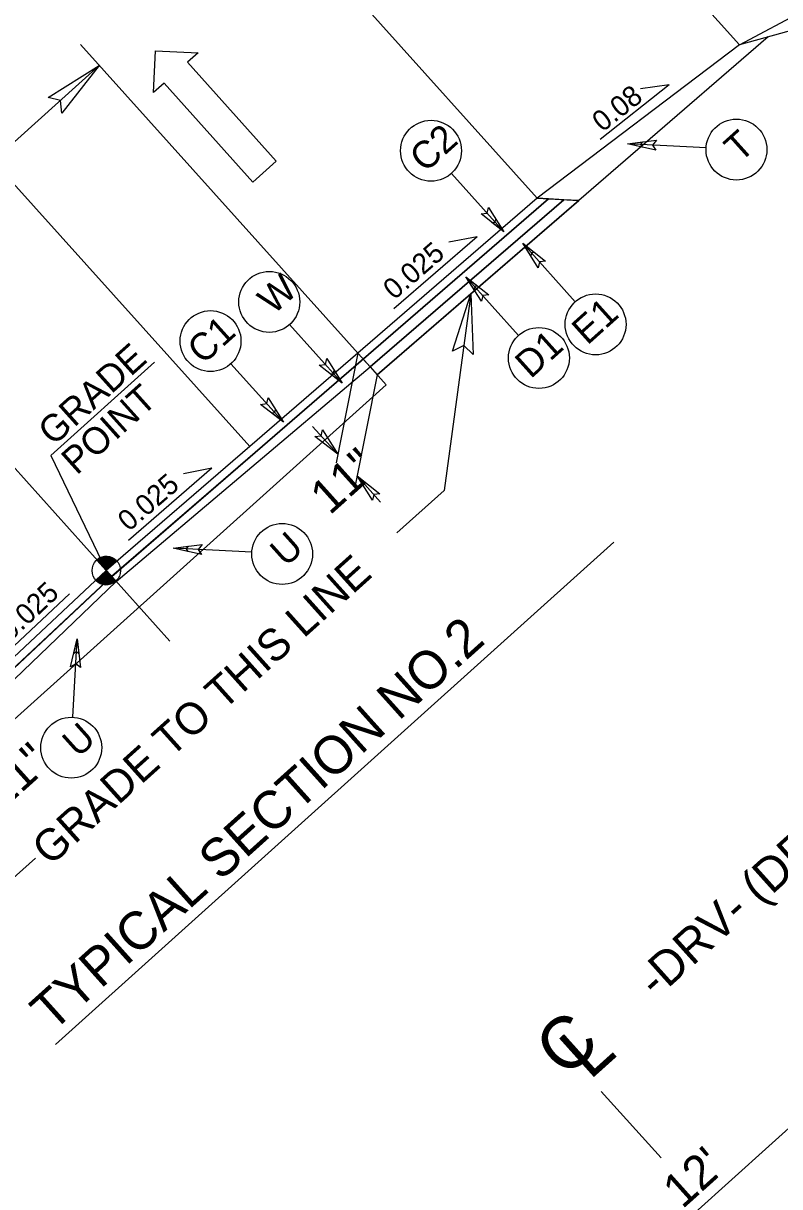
# Model space of a CAD drawing. Extents: x 2488411 to 2488707, y 383669 to 383962.
# Drawn here: x 2488444.6 to 2488468.51, y 383707.76 to 383744.52 of the extents above; entities that cross this region are included whole.
import ezdxf

# ---------------------------------------------------------------- set-up
doc = ezdxf.new("R2010")
doc.units = 0
for name, color, linetype in [('Old_Level_44', 7, 'Continuous'), ('Prop Dimension', 7, 'Continuous'), ('Prop DSN Text', 7, 'Continuous'), ('Prop Paint Stripe', 7, 'Continuous'), ('Prop Rip Rap Related Quantities Text', 7, 'Continuous'), ('Prop Roadway Bridge', 7, 'Continuous'), ('Prop Roadway Profile Bench Mark Info Text', 7, 'Continuous'), ('Prop ROW RW Lines', 7, 'Continuous'), ('Sheet Data Field CELL', 7, 'Continuous'), ('Sheet Data Text CELL', 7, 'Continuous'), ('Sheet Plan CELL', 7, 'Continuous'), ('Sheet Sticker Incomplete CELL', 7, 'Continuous'), ('Sheet Sticker Preliminary CELL', 7, 'Continuous'), ('Sheet Symbology CELL', 7, 'Continuous'), ('Sheet Title CELL', 7, 'Continuous'), ('Typical Hinge Slope Arterial CELL', 7, 'Continuous'), ('Typical Terminator CELL', 7, 'Continuous'), ('Typical Text Centerline CELL', 7, 'Continuous'), ('Typical Text ID Circle CELL', 7, 'Continuous')]:
    doc.layers.add(name, color=color, linetype=linetype)

msp = doc.modelspace()

# ---------------------------------------------------------------- linework, layer by layer
at = {"layer": 'Prop Dimension'}
for p, q in [((2488458.745, 383735.973), (2488457.907, 383729.763)), ((2488445.475, 383730.869), (2488448.747, 383733.811)), ((2488445.475, 383730.869), (2488447.226, 383727.229)), ((2488456.413, 383728.419), (2488457.907, 383729.763)), ((2488443.582, 383716.885), (2488444.986, 383718.147))]:
    msp.add_line(p, q, dxfattribs=at)
at = {"layer": 'Prop DSN Text'}
for p, q in [((2488466.185, 383740.581), (2488463.702, 383740.713)), ((2488458.134, 383739.776), (2488459.795, 383737.928)), ((2488462.051, 383735.721), (2488460.389, 383737.57)), ((2488460.258, 383734.66), (2488458.596, 383736.509)), ((2488453.02, 383735.002), (2488454.682, 383733.153)), ((2488451.164, 383733.763), (2488452.825, 383731.914)), ((2488451.826, 383727.806), (2488449.344, 383727.938)), ((2488446.169, 383722.594), (2488446.302, 383725.076))]:
    msp.add_line(p, q, dxfattribs=at)
for centre in [(2488457.491, 383740.491), (2488467.145, 383740.529), (2488452.378, 383735.717), (2488462.693, 383735.006), (2488450.521, 383734.478), (2488460.901, 383733.945), (2488452.786, 383727.754), (2488446.119, 383721.634)]:
    msp.add_circle(centre, 0.962, dxfattribs=at)
at = {"layer": 'Prop Paint Stripe'}
for points in [[(2488464.593, 383740.51), (2488463.702, 383740.713), (2488464.614, 383740.824), (2488464.491, 383740.671)], [(2488459.309, 383738.701), (2488459.795, 383737.928), (2488459.071, 383738.494), (2488459.267, 383738.516)], [(2488460.875, 383736.797), (2488460.389, 383737.57), (2488461.113, 383737.004), (2488460.917, 383736.982)], [(2488459.083, 383735.736), (2488458.596, 383736.509), (2488459.32, 383735.943), (2488459.124, 383735.921)], [(2488454.196, 383733.926), (2488454.682, 383733.153), (2488453.958, 383733.719), (2488454.154, 383733.741)], [(2488452.339, 383732.687), (2488452.825, 383731.914), (2488452.101, 383732.48), (2488452.297, 383732.502)], [(2488454.057, 383731.674), (2488454.543, 383730.901), (2488453.819, 383731.467), (2488454.015, 383731.488)], [(2488455.638, 383729.451), (2488455.152, 383730.224), (2488455.876, 383729.658), (2488455.68, 383729.636)], [(2488450.234, 383727.735), (2488449.344, 383727.938), (2488450.256, 383728.05), (2488450.133, 383727.896)], [(2488446.099, 383724.186), (2488446.302, 383725.076), (2488446.414, 383724.164), (2488446.26, 383724.287)]]:
    msp.add_lwpolyline(points, close=True, dxfattribs=at)
at = {"layer": 'Prop Rip Rap Related Quantities Text'}
for p, q in [((2488468.149, 383744.091), (2488455.784, 383733.415)), ((2488460.848, 383738.99), (2488451.766, 383731.149)), ((2488461.208, 383738.971), (2488451.93, 383730.959)), ((2488461.684, 383738.945), (2488455.563, 383733.661)), ((2488460.848, 383738.99), (2488462.159, 383738.92)), ((2488455.563, 383733.661), (2488455.342, 383733.906)), ((2488451.766, 383731.149), (2488447.226, 383727.229)), ((2488451.93, 383730.959), (2488447.39, 383727.04)), ((2488439.725, 383719.867), (2488447.397, 383727.046)), ((2488442.847, 383723.13), (2488447.226, 383727.229))]:
    msp.add_line(p, q, dxfattribs=at)
at = {"layer": 'Prop Roadway Bridge'}
for p, q in [((2488461.208, 383738.971), (2488455.342, 383733.906)), ((2488455.563, 383733.661), (2488461.684, 383738.945)), ((2488461.684, 383738.945), (2488461.208, 383738.971)), ((2488455.342, 383733.906), (2488455.563, 383733.661))]:
    msp.add_line(p, q, dxfattribs=at)
at = {"layer": 'Prop Roadway Profile Bench Mark Info Text'}
for p, q in [((2488465.017, 383742.579), (2488462.836, 383740.85)), ((2488465.017, 383742.579), (2488464.112, 383742.446)), ((2488458.951, 383737.777), (2488456.312, 383735.498)), ((2488458.951, 383737.777), (2488458.053, 383737.606)), ((2488450.563, 383730.461), (2488447.924, 383728.182)), ((2488450.563, 383730.461), (2488449.665, 383730.289)), ((2488443.509, 383724.104), (2488446.068, 383726.498))]:
    msp.add_line(p, q, dxfattribs=at)
at = {"layer": 'Prop ROW RW Lines'}
for p, q in [((2488448.72, 383742.327), (2488448.78, 383743.651)), ((2488448.78, 383743.651), (2488450.126, 383743.59)), ((2488450.126, 383743.59), (2488449.791, 383743.289)), ((2488449.791, 383743.289), (2488452.599, 383740.166)), ((2488449.055, 383742.627), (2488448.72, 383742.327)), ((2488451.863, 383739.504), (2488449.055, 383742.627)), ((2488452.599, 383740.166), (2488451.863, 383739.504))]:
    msp.add_line(p, q, dxfattribs=at)
at = {"layer": 'Sheet Data Field CELL'}
for p, q in [((2488460.848, 383738.99), (2488451.766, 383731.149)), ((2488451.93, 383730.959), (2488461.208, 383738.971)), ((2488461.208, 383738.971), (2488460.848, 383738.99)), ((2488451.766, 383731.149), (2488447.226, 383727.229)), ((2488447.397, 383727.046), (2488451.93, 383730.959)), ((2488439.725, 383719.867), (2488447.39, 383727.039)), ((2488447.226, 383727.229), (2488442.847, 383723.13)), ((2488447.39, 383727.04), (2488447.393, 383727.043)), ((2488447.393, 383727.043), (2488447.397, 383727.046))]:
    msp.add_line(p, q, dxfattribs=at)
for points in [[(2488447.39, 383727.039), (2488447.39, 383727.04)], [(2488447.397, 383727.046), (2488447.397, 383727.046)]]:
    msp.add_lwpolyline(points, dxfattribs=at)
at = {"layer": 'Sheet Data Text CELL'}
msp.add_line((2488445.621, 383712.259), (2488463.272, 383728.126), dxfattribs=at)
at = {"layer": 'Sheet Plan CELL'}
for p, q in [((2488467.241, 383743.842), (2488474.527, 383747.702)), ((2488479.685, 383747.266), (2488467.241, 383743.842))]:
    msp.add_line(p, q, dxfattribs=at)
at = {"layer": 'Sheet Sticker Incomplete CELL'}
msp.add_line((2488467.241, 383743.842), (2488460.848, 383738.99), dxfattribs=at)
at = {"layer": 'Sheet Sticker Preliminary CELL'}
for points in [[(2488445.392, 383742.171), (2488447.002, 383743.184), (2488445.823, 383741.676), (2488445.778, 383742.084)], [(2488464.166, 383740.607), (2488463.702, 383740.713), (2488464.177, 383740.771), (2488464.113, 383740.691)], [(2488459.542, 383738.331), (2488459.795, 383737.928), (2488459.418, 383738.223), (2488459.52, 383738.234)], [(2488460.642, 383737.167), (2488460.389, 383737.57), (2488460.766, 383737.275), (2488460.664, 383737.264)], [(2488458.85, 383736.106), (2488458.596, 383736.509), (2488458.973, 383736.214), (2488458.871, 383736.203)], [(2488458.175, 383734.158), (2488458.745, 383735.973), (2488458.823, 383734.06), (2488458.525, 383734.342)], [(2488454.429, 383733.556), (2488454.682, 383733.153), (2488454.305, 383733.448), (2488454.407, 383733.459)], [(2488452.572, 383732.317), (2488452.825, 383731.914), (2488452.448, 383732.209), (2488452.55, 383732.22)], [(2488449.807, 383727.832), (2488449.344, 383727.938), (2488449.819, 383727.996), (2488449.755, 383727.916)], [(2488446.197, 383724.612), (2488446.302, 383725.076), (2488446.36, 383724.601), (2488446.28, 383724.665)]]:
    msp.add_lwpolyline(points, close=True, dxfattribs=at)
at = {"layer": 'Sheet Symbology CELL'}
for p, q in [((2488461.684, 383738.945), (2488455.563, 383733.661)), ((2488458.745, 383735.972), (2488462.159, 383738.92)), ((2488462.159, 383738.92), (2488461.684, 383738.945)), ((2488455.784, 383733.415), (2488458.745, 383735.972)), ((2488458.745, 383735.972), (2488458.745, 383735.973)), ((2488455.342, 383733.906), (2488451.93, 383730.959)), ((2488455.563, 383733.661), (2488455.342, 383733.906)), ((2488447.537, 383726.883), (2488455.563, 383733.661)), ((2488455.563, 383733.661), (2488455.784, 383733.415)), ((2488439.946, 383719.622), (2488447.537, 383726.883))]:
    msp.add_line(p, q, dxfattribs=at)
for points in [[(2488458.745, 383735.973), (2488458.745, 383735.972)], [(2488451.93, 383730.959), (2488447.397, 383727.046), (2488447.393, 383727.043)], [(2488447.393, 383727.043), (2488447.39, 383727.039), (2488439.725, 383719.867)]]:
    msp.add_lwpolyline(points, dxfattribs=at)
at = {"layer": 'Sheet Title CELL'}
for p, q in [((2488467.241, 383743.842), (2488455.219, 383757.215)), ((2488460.848, 383738.99), (2488447.453, 383753.891)), ((2488455.563, 383733.661), (2488446.409, 383743.844)), ((2488431.385, 383729.145), (2488447.002, 383743.184)), ((2488451.766, 383731.149), (2488444.086, 383739.692)), ((2488455.175, 383734.092), (2488454.489, 383730.628)), ((2488455.784, 383733.415), (2488455.102, 383729.971)), ((2488454.543, 383730.901), (2488453.748, 383731.785)), ((2488455.899, 383729.393), (2488455.152, 383730.224)), ((2488461.637, 383703.179), (2488470.557, 383711.197))]:
    msp.add_line(p, q, dxfattribs=at)
at = {"layer": 'Typical Terminator CELL'}
for p, q in [((2488449.23, 383725), (2488439.562, 383735.755)), ((2488464.764, 383708.671), (2488462.874, 383710.773))]:
    msp.add_line(p, q, dxfattribs=at)
at = {"layer": 'Typical Text Centerline CELL'}
for p, q in [((2488446.928, 383727.562), (2488447.226, 383727.229)), ((2488447.226, 383727.229), (2488446.928, 383727.562)), ((2488447.559, 383727.528), (2488447.226, 383727.229)), ((2488446.893, 383726.93), (2488447.226, 383727.229)), ((2488447.226, 383727.229), (2488447.525, 383726.896))]:
    msp.add_line(p, q, dxfattribs=at)
for points in [[(2488447.305, 383727.299), (2488447.014, 383727.622)], [(2488447.311, 383727.305), (2488447.022, 383727.627)], [(2488447.318, 383727.311), (2488447.031, 383727.631)], [(2488447.325, 383727.317), (2488447.039, 383727.635)], [(2488447.331, 383727.323), (2488447.047, 383727.639)], [(2488447.338, 383727.329), (2488447.056, 383727.643)], [(2488447.345, 383727.335), (2488447.065, 383727.647)], [(2488447.351, 383727.341), (2488447.074, 383727.65)], [(2488447.358, 383727.347), (2488447.083, 383727.653)], [(2488447.365, 383727.353), (2488447.093, 383727.656)], [(2488447.371, 383727.359), (2488447.102, 383727.659)], [(2488447.378, 383727.365), (2488447.111, 383727.662)], [(2488447.385, 383727.371), (2488447.121, 383727.664)], [(2488447.391, 383727.377), (2488447.131, 383727.666)], [(2488447.398, 383727.383), (2488447.141, 383727.669)], [(2488447.404, 383727.389), (2488447.152, 383727.67)], [(2488447.411, 383727.395), (2488447.162, 383727.672)], [(2488447.418, 383727.401), (2488447.173, 383727.673)], [(2488447.424, 383727.407), (2488447.184, 383727.675)], [(2488447.431, 383727.413), (2488447.195, 383727.675)], [(2488447.438, 383727.419), (2488447.206, 383727.676)], [(2488447.444, 383727.425), (2488447.218, 383727.676)], [(2488447.451, 383727.431), (2488447.23, 383727.676)], [(2488447.458, 383727.437), (2488447.242, 383727.677)], [(2488447.464, 383727.443), (2488447.255, 383727.676)], [(2488447.471, 383727.449), (2488447.268, 383727.674)], [(2488447.478, 383727.455), (2488447.282, 383727.673)], [(2488447.484, 383727.461), (2488447.296, 383727.671)], [(2488447.491, 383727.467), (2488447.309, 383727.669)], [(2488447.498, 383727.473), (2488447.324, 383727.666)], [(2488447.504, 383727.479), (2488447.339, 383727.662)], [(2488447.511, 383727.485), (2488447.355, 383727.658)], [(2488447.518, 383727.491), (2488447.373, 383727.652)], [(2488447.524, 383727.497), (2488447.391, 383727.645)], [(2488447.531, 383727.503), (2488447.41, 383727.637)], [(2488447.538, 383727.509), (2488447.431, 383727.628)], [(2488447.231, 383727.233), (2488446.932, 383727.566), (2488446.932, 383727.566)], [(2488447.238, 383727.239), (2488446.939, 383727.572)], [(2488447.245, 383727.245), (2488446.946, 383727.577)], [(2488447.251, 383727.251), (2488446.953, 383727.583)], [(2488447.258, 383727.257), (2488446.96, 383727.589)], [(2488447.265, 383727.263), (2488446.967, 383727.594)], [(2488447.271, 383727.269), (2488446.975, 383727.599)], [(2488447.278, 383727.275), (2488446.983, 383727.604)], [(2488447.285, 383727.281), (2488446.99, 383727.609)], [(2488447.291, 383727.287), (2488446.998, 383727.613)], [(2488447.298, 383727.293), (2488447.006, 383727.618)], [(2488447.544, 383727.515), (2488447.455, 383727.614)], [(2488447.551, 383727.521), (2488447.483, 383727.596)], [(2488447.558, 383727.527), (2488447.525, 383727.563)], [(2488446.94, 383726.885), (2488446.897, 383726.933)], [(2488446.977, 383726.857), (2488446.904, 383726.939)], [(2488447.004, 383726.841), (2488446.91, 383726.945)], [(2488447.027, 383726.828), (2488446.917, 383726.951)], [(2488447.048, 383726.818), (2488446.924, 383726.957)], [(2488447.067, 383726.81), (2488446.93, 383726.963)], [(2488447.085, 383726.805), (2488446.937, 383726.969)], [(2488447.101, 383726.799), (2488446.944, 383726.975)], [(2488447.117, 383726.795), (2488446.95, 383726.981)], [(2488447.133, 383726.791), (2488446.957, 383726.987)], [(2488447.147, 383726.789), (2488446.964, 383726.993)], [(2488447.161, 383726.786), (2488446.97, 383726.999)], [(2488447.175, 383726.784), (2488446.977, 383727.005)], [(2488447.188, 383726.783), (2488446.984, 383727.011)], [(2488447.201, 383726.782), (2488446.99, 383727.017)], [(2488447.214, 383726.781), (2488446.997, 383727.023)], [(2488447.226, 383726.782), (2488447.004, 383727.029)], [(2488447.238, 383726.782), (2488447.01, 383727.035)], [(2488447.25, 383726.782), (2488447.017, 383727.041)], [(2488447.261, 383726.782), (2488447.024, 383727.047)], [(2488447.272, 383726.784), (2488447.03, 383727.053)], [(2488447.283, 383726.785), (2488447.037, 383727.059)], [(2488447.294, 383726.786), (2488447.044, 383727.065)], [(2488447.304, 383726.788), (2488447.05, 383727.07)], [(2488447.314, 383726.79), (2488447.057, 383727.076)], [(2488447.324, 383726.792), (2488447.063, 383727.082)], [(2488447.334, 383726.795), (2488447.07, 383727.088)], [(2488447.344, 383726.797), (2488447.077, 383727.094)], [(2488447.353, 383726.8), (2488447.083, 383727.1)], [(2488447.363, 383726.803), (2488447.09, 383727.106)], [(2488447.372, 383726.806), (2488447.097, 383727.112)], [(2488447.381, 383726.809), (2488447.103, 383727.118)], [(2488447.391, 383726.812), (2488447.11, 383727.124)], [(2488447.399, 383726.816), (2488447.117, 383727.13)], [(2488447.408, 383726.82), (2488447.123, 383727.136)], [(2488447.417, 383726.824), (2488447.13, 383727.142)], [(2488447.425, 383726.828), (2488447.137, 383727.148)], [(2488447.433, 383726.832), (2488447.143, 383727.154)], [(2488447.441, 383726.836), (2488447.15, 383727.16)], [(2488447.449, 383726.841), (2488447.157, 383727.166)], [(2488447.457, 383726.845), (2488447.163, 383727.172)], [(2488447.465, 383726.85), (2488447.17, 383727.178)], [(2488447.473, 383726.855), (2488447.177, 383727.184)], [(2488447.48, 383726.86), (2488447.183, 383727.19)], [(2488447.487, 383726.866), (2488447.19, 383727.196)], [(2488447.495, 383726.871), (2488447.197, 383727.202)], [(2488447.502, 383726.876), (2488447.203, 383727.208)], [(2488447.508, 383726.882), (2488447.21, 383727.214)], [(2488447.516, 383726.887), (2488447.217, 383727.22)], [(2488447.522, 383726.893), (2488447.522, 383726.893), (2488447.223, 383727.226)]]:
    msp.add_lwpolyline(points, dxfattribs=at)
msp.add_circle((2488447.227, 383727.229), 0.448, dxfattribs=at)
for start, end in [(41.9443, 131.9443), (221.9443, 311.9443)]:
    msp.add_arc((2488447.227, 383727.229), 0.448, start, end, dxfattribs=at)
at = {"layer": 'Typical Text ID Circle CELL'}
for p, q in [((2488447.537, 383726.883), (2488455.563, 383733.661)), ((2488456.069, 383733.098), (2488455.563, 383733.661)), ((2488440.451, 383719.059), (2488456.069, 383733.098)), ((2488439.946, 383719.622), (2488447.537, 383726.883))]:
    msp.add_line(p, q, dxfattribs=at)

# ---------------------------------------------------------------- texts
at = {"layer": 'Old_Level_44'}
for s, height, p in [('C2', 0.8608, (2488457.302, 383739.775)), ('T', 0.861, (2488467.253, 383740.094)), ('W', 0.861, (2488452.506, 383735.286)), ('E1', 0.8608, (2488462.431, 383734.327)), ('C1', 0.8608, (2488450.277, 383733.711)), ('D1', 0.8608, (2488460.638, 383733.266)), ('U', 0.861, (2488452.895, 383727.319)), ('U', 0.861, (2488446.33, 383721.291))]:
    msp.add_text(s, height=height, rotation=41.9538, dxfattribs=at).set_placement(p)
at = {"layer": 'Prop Dimension'}
for s, height, p in [('GRADE', 0.85, (2488445.553, 383731.142)), ('POINT', 0.85, (2488446.291, 383730.221)), ('GRADE TO THIS LINE', 1, (2488445.451, 383717.867))]:
    msp.add_text(s, height=height, rotation=41.9538, dxfattribs=at).set_placement(p)
at = {"layer": 'Prop Roadway Profile Bench Mark Info Text'}
for s, rotation, p in [('0.08', 38.4053, (2488462.909, 383741.062)), ('0.025', 40.8081, (2488456.327, 383735.758)), ('0.025', 40.8081, (2488447.939, 383728.442)), ('0.025', 43.0996, (2488444.192, 383724.977))]:
    msp.add_text(s, height=0.6476, rotation=rotation, dxfattribs=at).set_placement(p)
at = {"layer": 'Sheet Data Text CELL'}
msp.add_text('TYPICAL SECTION NO.2  ', height=1.2, rotation=41.9538, dxfattribs=at).set_placement((2488445.525, 383712.624))
at = {"layer": 'Sheet Title CELL'}
for s, p in [('11"', (2488454.291, 383728.957)), ('-DRV- (DRIVEWAY)', (2488464.613, 383713.691)), ('11"', (2488443.935, 383719.647)), ("12'", (2488465.435, 383707.037))]:
    msp.add_text(s, height=1.0817, rotation=41.9538, dxfattribs=at).set_placement(p)
at = {"layer": 'Typical Hinge Slope Arterial CELL'}
for s, height, rotation, p in [('C', 1.64, 41.9538, (2488461.725, 383711.159)), ('L', 1.641, 41.9007, (2488462.505, 383711.107))]:
    msp.add_text(s, height=height, rotation=rotation, dxfattribs=at).set_placement(p)

doc.saveas('drawing.dxf')
